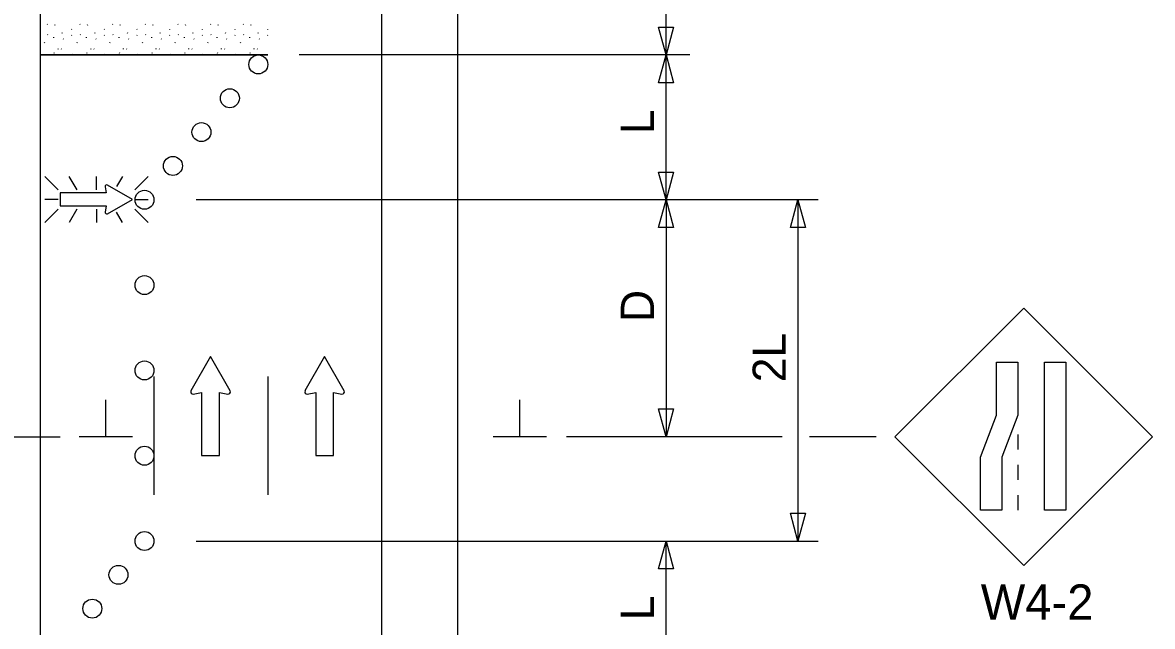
# Model space of a CAD drawing. Extents: x 16590 to 19508, y 5703 to 6974.
# Drawn here: x 17913.2 to 18151.5, y 6568 to 6695.4 of the extents above; entities that cross this region are included whole.
import ezdxf

# ---------------------------------------------------------------- set-up
doc = ezdxf.new("R2010")
doc.units = 0
for name, color, linetype in [('ALI_LEGAL_EX', 7, 'Continuous'), ('MT_SCRATCH_LEVEL_A', 7, 'Continuous'), ('MT_SCRATCH_LEVEL_E', 7, 'Continuous'), ('PAVT_EDGE_EX', 7, 'Continuous'), ('TRAFFIC_SIGNS_PR', 7, 'Continuous'), ('TYPICAL_TEXT_DIMEN_PR', 7, 'Continuous')]:
    doc.layers.add(name, color=color, linetype=linetype)

msp = doc.modelspace()

# ---------------------------------------------------------------- linework, layer by layer
at = {"layer": 'ALI_LEGAL_EX'}
for points in [[(17940.96, 6620.69), (17940.96, 6595.69)], [(17964.96, 6620.69), (17964.96, 6595.69)]]:
    msp.add_lwpolyline(points, dxfattribs=at)
at = {"layer": 'MT_SCRATCH_LEVEL_A'}
msp.add_line((17964.96, 6688.54), (17916.96, 6688.54), dxfattribs=at)
at = {"layer": 'MT_SCRATCH_LEVEL_E'}
for p, q in [((17952.86, 6624.9), (17948.75, 6617.66)), ((17957.01, 6617.66), (17952.86, 6624.9)), ((17976.91, 6624.9), (17972.8, 6617.66)), ((17981.06, 6617.66), (17976.91, 6624.9)), ((17949.23, 6616.98), (17951.01, 6617.29)), ((17951.01, 6617.29), (17951.01, 6604.03)), ((17954.75, 6604.03), (17954.75, 6617.29)), ((17954.75, 6617.29), (17956.53, 6616.98)), ((17973.28, 6616.98), (17975.06, 6617.29)), ((17975.06, 6617.29), (17975.06, 6604.03)), ((17978.8, 6604.03), (17978.8, 6617.29)), ((17978.8, 6617.29), (17980.58, 6616.98)), ((17951.01, 6604.03), (17954.75, 6604.03)), ((17975.06, 6604.03), (17978.8, 6604.03))]:
    msp.add_line(p, q, dxfattribs=at)
for centre, start, end in [((17949.16, 6617.43), 150.4248, 279.9638), ((17956.6, 6617.43), 260.0362, 29.7731), ((17973.21, 6617.43), 150.4248, 279.9638), ((17980.65, 6617.43), 260.0362, 29.7731)]:
    msp.add_arc(centre, 0.463, start, end, dxfattribs=at)
at = {"layer": 'PAVT_EDGE_EX'}
for p, q in [((17916.96, 6925.33), (17916.96, 6268.58)), ((17988.96, 6925.33), (17988.96, 6268.58)), ((18004.96, 6925.33), (18004.96, 6268.58)), ((17916.96, 6717.96), (17916.96, 6688.54)), ((17918.45, 6695.06), (17918.51, 6694.98)), ((17919.98, 6694.92), (17920.04, 6694.84)), ((17921.63, 6693.13), (17921.68, 6693.25)), ((17923.55, 6694), (17923.6, 6693.92)), ((17925.34, 6695.06), (17925.39, 6694.98)), ((17926.87, 6694.92), (17926.92, 6694.84)), ((17928.51, 6693.13), (17928.56, 6693.25)), ((17930.44, 6694), (17930.49, 6693.92)), ((17932.23, 6695.06), (17932.28, 6694.98)), ((17933.76, 6694.92), (17933.81, 6694.84)), ((17935.4, 6693.13), (17935.45, 6693.25)), ((17937.33, 6694), (17937.38, 6693.92)), ((17939.12, 6695.06), (17939.17, 6694.98)), ((17940.65, 6694.92), (17940.7, 6694.84)), ((17942.29, 6693.13), (17942.34, 6693.25)), ((17944.21, 6694), (17944.26, 6693.92)), ((17946, 6695.06), (17946.06, 6694.98)), ((17947.53, 6694.92), (17947.59, 6694.84)), ((17949.18, 6693.13), (17949.23, 6693.25)), ((17951.1, 6694), (17951.15, 6693.92)), ((17952.89, 6695.06), (17952.94, 6694.98)), ((17954.42, 6694.92), (17954.47, 6694.84)), ((17956.06, 6693.13), (17956.12, 6693.25)), ((17957.99, 6694), (17958.04, 6693.92)), ((17959.78, 6695.06), (17959.83, 6694.98)), ((17961.31, 6694.92), (17961.36, 6694.84)), ((17962.95, 6693.13), (17963, 6693.25)), ((17964.88, 6694), (17964.93, 6693.92)), ((17917.88, 6691.1), (17917.94, 6691.21)), ((17918.5, 6692.85), (17918.55, 6692.77)), ((17919.78, 6692.27), (17919.8, 6692.16)), ((17921.81, 6691.93), (17921.87, 6691.85)), ((17923.59, 6692.6), (17923.65, 6692.72)), ((17924.77, 6691.1), (17924.82, 6691.21)), ((17925.39, 6692.85), (17925.44, 6692.77)), ((17926.67, 6692.27), (17926.69, 6692.16)), ((17928.7, 6691.93), (17928.75, 6691.85)), ((17930.48, 6692.6), (17930.53, 6692.72)), ((17931.66, 6691.1), (17931.71, 6691.21)), ((17932.28, 6692.85), (17932.33, 6692.77)), ((17933.56, 6692.27), (17933.57, 6692.16)), ((17935.59, 6691.93), (17935.64, 6691.85)), ((17937.37, 6692.6), (17937.42, 6692.72)), ((17938.55, 6691.1), (17938.6, 6691.21)), ((17939.17, 6692.85), (17939.22, 6692.77)), ((17940.45, 6692.27), (17940.46, 6692.16)), ((17942.48, 6691.93), (17942.53, 6691.85)), ((17944.26, 6692.6), (17944.31, 6692.72)), ((17945.43, 6691.1), (17945.49, 6691.21)), ((17946.05, 6692.85), (17946.1, 6692.77)), ((17947.33, 6692.27), (17947.35, 6692.16)), ((17949.36, 6691.93), (17949.42, 6691.85)), ((17951.14, 6692.6), (17951.19, 6692.72)), ((17952.32, 6691.1), (17952.37, 6691.21)), ((17952.94, 6692.85), (17952.99, 6692.77)), ((17954.22, 6692.27), (17954.24, 6692.16)), ((17956.25, 6691.93), (17956.3, 6691.85)), ((17958.03, 6692.6), (17958.08, 6692.72)), ((17959.21, 6691.1), (17959.26, 6691.21)), ((17959.83, 6692.85), (17959.88, 6692.77)), ((17961.11, 6692.27), (17961.12, 6692.16)), ((17963.14, 6691.93), (17963.19, 6691.85)), ((17964.92, 6692.6), (17964.96, 6692.69)), ((17916.96, 6688.54), (17964.96, 6688.54)), ((17919.9, 6688.9), (17919.96, 6689.02)), ((17920.67, 6689.86), (17920.72, 6689.78)), ((17921.4, 6689.83), (17921.46, 6689.75)), ((17923.72, 6688.6), (17923.78, 6688.72)), ((17926.79, 6688.9), (17926.84, 6689.02)), ((17927.56, 6689.86), (17927.61, 6689.78)), ((17928.29, 6689.83), (17928.35, 6689.75)), ((17930.61, 6688.6), (17930.66, 6688.72)), ((17933.68, 6688.9), (17933.73, 6689.02)), ((17934.44, 6689.86), (17934.49, 6689.78)), ((17935.18, 6689.83), (17935.23, 6689.75)), ((17937.5, 6688.6), (17937.55, 6688.72)), ((17940.57, 6688.9), (17940.62, 6689.02)), ((17941.33, 6689.86), (17941.38, 6689.78)), ((17942.07, 6689.83), (17942.12, 6689.75)), ((17944.39, 6688.6), (17944.44, 6688.72)), ((17947.45, 6688.9), (17947.51, 6689.02)), ((17948.22, 6689.86), (17948.27, 6689.78)), ((17948.96, 6689.83), (17949.01, 6689.75)), ((17951.27, 6688.6), (17951.33, 6688.72)), ((17954.34, 6688.9), (17954.39, 6689.02)), ((17955.11, 6689.86), (17955.16, 6689.78)), ((17955.84, 6689.83), (17955.9, 6689.75)), ((17958.16, 6688.6), (17958.21, 6688.72)), ((17961.23, 6688.9), (17961.28, 6689.02)), ((17961.99, 6689.86), (17962.05, 6689.78)), ((17962.73, 6689.83), (17962.78, 6689.75))]:
    msp.add_line(p, q, dxfattribs=at)
at = {"layer": 'TRAFFIC_SIGNS_PR'}
for p, q in [((17920.73, 6660.07), (17917.91, 6662.9)), ((17923.03, 6662.9), (17924.66, 6660.07)), ((17928.82, 6660.07), (17928.82, 6662.9)), ((17934.29, 6662.9), (17933.08, 6660.8)), ((17939.72, 6662.89), (17936.9, 6660.07)), ((17920.73, 6658.04), (17917.91, 6658.04)), ((17936.9, 6658.04), (17939.72, 6658.04)), ((17920.73, 6656.01), (17917.91, 6653.19)), ((17924.68, 6656.01), (17923.05, 6653.19)), ((17928.82, 6656.01), (17928.82, 6653.19)), ((17933, 6655.38), (17934.26, 6653.19)), ((17939.72, 6653.19), (17936.9, 6656.01)), ((18124.37, 6635.12), (18097.21, 6607.97)), ((18151.52, 6607.97), (18124.37, 6635.12)), ((18097.21, 6607.97), (18124.37, 6580.82)), ((18123.12, 6608.46), (18123.12, 6605.26)), ((18124.37, 6580.82), (18151.52, 6607.97)), ((18123.12, 6602.06), (18123.12, 6598.86)), ((18123.12, 6595.66), (18123.12, 6592.46))]:
    msp.add_line(p, q, dxfattribs=at)
for points in [[(17930.64, 6660.73), (17930.87, 6659.43), (17921.15, 6659.43), (17921.15, 6656.69), (17930.87, 6656.69), (17930.64, 6655.38)], [(17931.14, 6655.03), (17936.45, 6658.04), (17931.14, 6661.08)]]:
    msp.add_lwpolyline(points, dxfattribs=at)
for points in [[(18123.12, 6623.71), (18123.12, 6612.53), (18119.78, 6603.64), (18119.78, 6592.46), (18115.28, 6592.46), (18115.28, 6603.64), (18118.63, 6612.53), (18118.63, 6623.71)], [(18133.26, 6623.71), (18133.26, 6592.46), (18128.76, 6592.46), (18128.76, 6623.71)]]:
    msp.add_lwpolyline(points, close=True, dxfattribs=at)
for centre in [(17962.96, 6686.53), (17956.96, 6679.39), (17950.96, 6672.25), (17944.96, 6665.11), (17938.96, 6657.97), (17938.96, 6639.97), (17938.96, 6621.97), (17938.96, 6603.97), (17938.96, 6585.97), (17933.46, 6578.84), (17927.96, 6571.71)]:
    msp.add_circle(centre, 2, dxfattribs=at)
for centre, start, end in [((17930.98, 6660.78), 61.4833, 189.9593), ((17930.98, 6655.33), 170.7308, 298.8916)]:
    msp.add_arc(centre, 0.341, start, end, dxfattribs=at)
at = {"layer": 'TYPICAL_TEXT_DIMEN_PR'}
for p, q in [((18048.96, 6688.54), (18048.96, 6717.96)), ((18048.96, 6688.54), (18047.39, 6694.4)), ((18047.39, 6694.4), (18048.96, 6694.4)), ((18048.96, 6694.4), (18050.53, 6694.4)), ((18050.53, 6694.4), (18048.96, 6688.54)), ((18053.96, 6688.54), (17971.56, 6688.54)), ((18047.39, 6682.67), (18048.96, 6688.54)), ((18048.96, 6657.97), (18048.96, 6688.54)), ((18048.96, 6688.54), (18050.53, 6682.67)), ((18048.96, 6682.67), (18047.39, 6682.67)), ((18050.53, 6682.67), (18048.96, 6682.67)), ((18048.96, 6657.97), (18047.39, 6663.83)), ((18047.39, 6663.83), (18048.96, 6663.83)), ((18048.96, 6663.83), (18050.53, 6663.83)), ((18050.53, 6663.83), (18048.96, 6657.97)), ((18081, 6657.97), (17949.86, 6657.97)), ((18047.39, 6652.11), (18048.96, 6657.97)), ((18048.96, 6657.97), (18048.96, 6607.97)), ((18048.96, 6657.97), (18050.53, 6652.11)), ((18075.19, 6652.11), (18076.76, 6657.97)), ((18076.76, 6657.97), (18078.33, 6652.11)), ((18076.76, 6657.97), (18076.76, 6585.97)), ((18048.96, 6652.11), (18047.39, 6652.11)), ((18050.53, 6652.11), (18048.96, 6652.11)), ((18076.76, 6652.11), (18075.19, 6652.11)), ((18078.33, 6652.11), (18076.76, 6652.11)), ((17930.81, 6607.97), (17930.81, 6615.76)), ((18018.08, 6607.97), (18018.08, 6615.76)), ((18048.96, 6607.97), (18047.39, 6613.83)), ((18047.39, 6613.83), (18048.96, 6613.83)), ((18048.96, 6613.83), (18050.53, 6613.83)), ((18050.53, 6613.83), (18048.96, 6607.97)), ((18076.76, 6612.84), (18076.76, 6609.07)), ((17858.57, 6607.97), (17921.15, 6607.97)), ((17936.43, 6607.97), (17925.18, 6607.97)), ((18023.71, 6607.97), (18012.46, 6607.97)), ((18073.45, 6607.97), (18027.96, 6607.97)), ((18093.23, 6607.97), (18079.22, 6607.97)), ((18076.76, 6585.97), (18075.19, 6591.83)), ((18075.19, 6591.83), (18076.76, 6591.83)), ((18076.76, 6591.83), (18078.33, 6591.83)), ((18078.33, 6591.83), (18076.76, 6585.97)), ((17949.86, 6585.97), (18081, 6585.97)), ((18047.39, 6580.11), (18048.96, 6585.97)), ((18048.96, 6555.41), (18048.96, 6585.97)), ((18048.96, 6585.97), (18050.53, 6580.11)), ((18048.96, 6580.11), (18047.39, 6580.11)), ((18050.53, 6580.11), (18048.96, 6580.11))]:
    msp.add_line(p, q, dxfattribs=at)

# ---------------------------------------------------------------- texts
at = {"layer": 'TRAFFIC_SIGNS_PR'}
msp.add_text('W4-2', height=7.44, dxfattribs=at).set_placement((18115.32, 6569.38))
at = {"layer": 'TYPICAL_TEXT_DIMEN_PR'}
for s, p in [('L', (18046.4, 6671.83)), ('D', (18046.4, 6632.19)), ('2L', (18074.21, 6619.47)), ('L', (18046.4, 6569.26))]:
    msp.add_text(s, height=7, rotation=90, dxfattribs=at).set_placement(p)

doc.saveas('drawing.dxf')
